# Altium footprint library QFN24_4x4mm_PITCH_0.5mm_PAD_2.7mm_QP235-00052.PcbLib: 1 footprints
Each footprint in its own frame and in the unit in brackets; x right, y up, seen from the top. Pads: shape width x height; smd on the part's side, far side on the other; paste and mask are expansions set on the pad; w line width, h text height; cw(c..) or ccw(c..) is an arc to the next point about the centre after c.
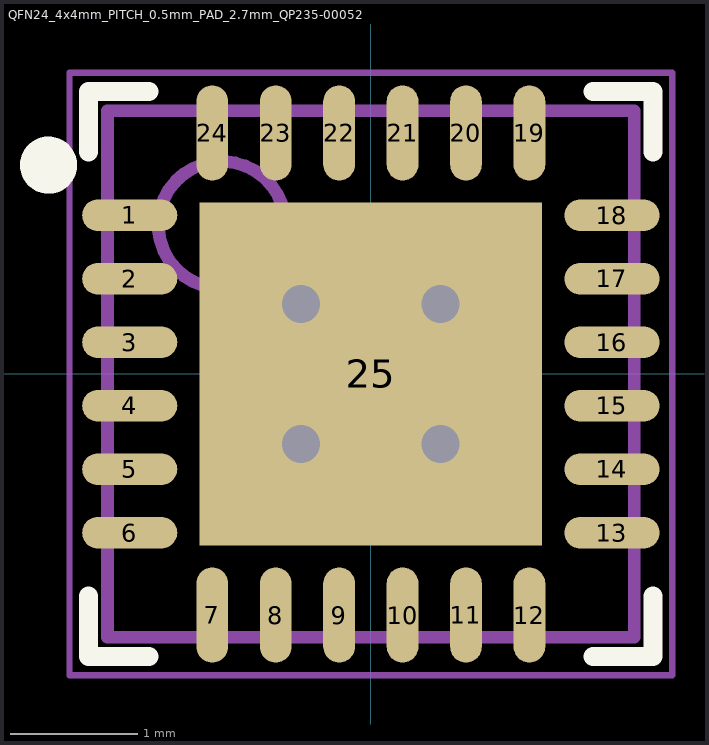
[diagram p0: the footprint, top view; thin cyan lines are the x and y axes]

## QFN24_4x4mm_PITCH_0.5mm_PAD_2.7mm_QP235-00052 [mm] "QFN, 24-Leads, Body 4.00x4.00mm, Pitch 0.50mm, Thermal Pad 2.70x2.70mm, IPC High Density"
height 1
pads (25):
  oval 0.75x0.25 smd: 1(-1.9,1.25) 2(-1.9,0.75) 3(-1.9,0.25) 4(-1.9,-0.25) 5(-1.9,-0.75) 6(-1.9,-1.25) 13(1.9,-1.25) 14(1.9,-0.75) 15(1.9,-0.25) 16(1.9,0.25) 17(1.9,0.75) 18(1.9,1.25)
  oval 0.25x0.75 smd: 7(-1.25,-1.9) 8(-0.75,-1.9) 9(-0.25,-1.9) 10(0.25,-1.9) 11(0.75,-1.9) 12(1.25,-1.9) 19(1.25,1.9) 20(0.75,1.9) 21(0.25,1.9) 22(-0.25,1.9) 23(-0.75,1.9) 24(-1.25,1.9)
  rect 2.7x2.7 smd: 25(0,0)
via 0.55,-0.55 diameter 0.7 hole 0.3
via -0.55,-0.55 diameter 0.7 hole 0.3
via 0.55,0.55 diameter 0.7 hole 0.3
via -0.55,0.55 diameter 0.7 hole 0.3
Top Overlay:
  circle w0.25: c-2.54,1.646 r0.1
  lines w0.15: -2.225,-1.75 -2.225,-2.225 -1.75,-2.225 ; -2.225,1.75 -2.225,2.225 -1.75,2.225 ; 1.75,-2.225 2.225,-2.225 2.225,-1.75 ; 1.75,2.225 2.225,2.225 2.225,1.75
Mechanical 13:
  circle w0.1: c-1.175,1.175 r0.5
  lines w0.1: -2.075,-2.075 2.075,-2.075 2.075,2.075 -2.075,2.075 -2.075,-2.075
Mechanical 15:
  lines w0.05: -2.375,-2.375 2.375,-2.375 2.375,2.375 -2.375,2.375 -2.375,-2.375
  lines w0.1: -0.5,0 0.5,0 ; 0,-0.5 0,0.5
3D body "QFN50P400X400X100_HS-25L.step": height 1, standoff 0, extent -2.076,-2.076 2.076,2.076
